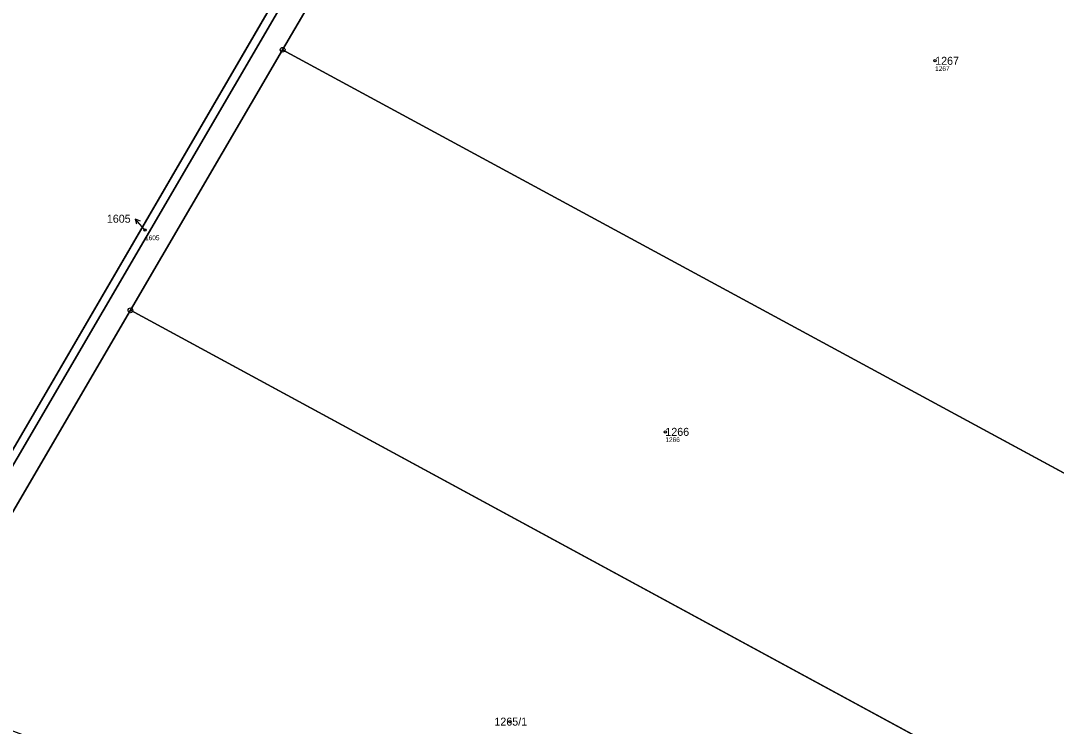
# Model space of a CAD drawing. Extents: x -658203 to -653176, y -1156738 to -1151709.
# Drawn here: x -654131.6 to -653911.6, y -1153519.4 to -1153369.6 of the extents above; entities that cross this region are included whole.
import ezdxf

# ---------------------------------------------------------------- set-up
doc = ezdxf.new("R2010")
doc.units = 0
for name, color, linetype in [('Vrstva 1', 7, 'Continuous'), ('Vrstva 2', 7, 'Continuous'), ('Vrstva 50', 7, 'Continuous'), ('Vrstva 51', 7, 'Continuous'), ('Vrstva 7', 7, 'Continuous'), ('Vrstva 8', 7, 'Continuous')]:
    doc.layers.add(name, color=color, linetype=linetype)

msp = doc.modelspace()

# ---------------------------------------------------------------- linework, layer by layer
at = {"layer": 'Vrstva 1'}
for p, q in [((-654043.59, -1153306.75), (-654134.69, -1153463.12)), ((-654108.26, -1153431.12), (-654075.93, -1153375.79)), ((-654075.93, -1153375.79), (-653868.48, -1153488.12)), ((-654155.6, -1153512.14), (-654108.26, -1153431.12)), ((-654108.26, -1153431.12), (-653913.06, -1153536.89))]:
    msp.add_line(p, q, dxfattribs=at)
for points in [[(-654013.78, -1153269.44), (-654063.57, -1153354.64), (-654075.93, -1153375.79)], [(-654160.33, -1153510.27), (-654067.87, -1153352.06), (-654042.35, -1153308.39), (-654037.81, -1153300.62)]]:
    msp.add_lwpolyline(points, dxfattribs=at)
at = {"layer": 'Vrstva 50'}
for centre in [(-653937.31, -1153378.14), (-654105.17, -1153414.07), (-653994.63, -1153456.93), (-654027.64, -1153518.46)]:
    msp.add_circle(centre, 0.25, dxfattribs=at)
at = {"layer": 'Vrstva 51'}
for points in [[(-654108.26, -1153431.12), (-654075.93, -1153375.79), (-654063.57, -1153354.64), (-654013.78, -1153269.44), (-653953.23, -1153165.8), (-653942.94, -1153148.19), (-653894.24, -1153064.84), (-653881.38, -1153042.83), (-653828.15, -1152951.83), (-653822.4, -1152951.85), (-653835.43, -1152944.52), (-653832.41, -1152949.22), (-653885.7, -1153040.3), (-653953.52, -1153156.56), (-653957.64, -1153163.43), (-653959.15, -1153166.02), (-654009.36, -1153251.95), (-654037.81, -1153300.62), (-654042.35, -1153308.39), (-654067.87, -1153352.06), (-654160.33, -1153510.27), (-654161.91, -1153512.94), (-654157.11, -1153514.73), (-654155.6, -1153512.14)], [(-654303.07, -1153432.36), (-654134.69, -1153463.12), (-654043.59, -1153306.75), (-654045.64, -1153304.05), (-654185.29, -1153229.37)], [(-654011.1, -1153250.98), (-654040.25, -1153301.01), (-654043.59, -1153306.75), (-654134.69, -1153463.12), (-654135.74, -1153464.92), (-654159.85, -1153506.31), (-654161.98, -1153509.97), (-654160.33, -1153510.27), (-654067.87, -1153352.06), (-654042.35, -1153308.39), (-654037.81, -1153300.62), (-654009.36, -1153251.95)], [(-653868.48, -1153488.12), (-653819.34, -1153439.55), (-653776.99, -1153397.7), (-654013.78, -1153269.44), (-654063.57, -1153354.64), (-654075.93, -1153375.79)], [(-653913.06, -1153536.89), (-653907.67, -1153526.85), (-653868.48, -1153488.12), (-654075.93, -1153375.79), (-654108.26, -1153431.12)], [(-653936.32, -1153592.35), (-653935.72, -1153579.05), (-653913.06, -1153536.89), (-654108.26, -1153431.12), (-654155.6, -1153512.14), (-653996.17, -1153571.43), (-653970.19, -1153592.89), (-653961.05, -1153594.49), (-653949.9, -1153594.09)]]:
    msp.add_lwpolyline(points, close=True, dxfattribs=at)
at = {"layer": 'Vrstva 7'}
for p, q in [((-654105.29, -1153413.93), (-654107.26, -1153411.67)), ((-654107.26, -1153411.67), (-654106.22, -1153412.09)), ((-654107.26, -1153411.67), (-654106.98, -1153412.75)), ((-654105.17, -1153414.07), (-654105.29, -1153413.93))]:
    msp.add_line(p, q, dxfattribs=at)
at = {"layer": 'Vrstva 8'}
for centre, radius in [((-654075.93, -1153375.79), 0.5), ((-654075.93, -1153375.79), 0.0303), ((-654108.26, -1153431.12), 0.5), ((-654108.26, -1153431.12), 0.0303)]:
    msp.add_circle(centre, radius, dxfattribs=at)

# ---------------------------------------------------------------- texts
at = {"layer": 'Vrstva 2'}
for s, p in [('1267', (-653937.31, -1153378.99)), ('1605', (-654113.28, -1153412.52)), ('1266', (-653994.63, -1153457.78)), ('1265/1', (-654030.95, -1153519.31))]:
    msp.add_text(s, height=1.7, dxfattribs=at).set_placement(p)
at = {"layer": 'Vrstva 50'}
for s, p in [('1267', (-653937.31, -1153380.3)), ('1605', (-654105.17, -1153416.23)), ('1266', (-653994.63, -1153459.09))]:
    msp.add_text(s, height=1, dxfattribs=at).set_placement(p)

doc.saveas('drawing.dxf')
